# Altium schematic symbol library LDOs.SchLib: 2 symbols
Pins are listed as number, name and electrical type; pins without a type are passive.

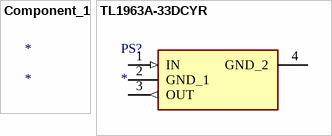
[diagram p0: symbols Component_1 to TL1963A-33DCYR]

## Component_1
designator *

## TL1963A-33DCYR
designator PS?
Power Supply; Manufacturer_Name: Texas Instruments; Manufacturer_Part_Number: TL1963A-33DCYR; Description: 1.5-A Low-Noise Fast-Transient-Response Low-Dropout Regulator
footprint SOT230P700X180-4N
pins: 1 IN (in), 2 GND_1 (power), 3 OUT (out), 4 GND_2 (power)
